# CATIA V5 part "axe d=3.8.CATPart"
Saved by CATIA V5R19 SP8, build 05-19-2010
Part number: axe d=3.8
Revision: ANY
Definition: UNKNOWN
Nomenclature: axe d=3.8
Source: Unknown
Bounding box of the stored display mesh (mm): x 0 to 16, y -3 to 3, z -3 to 3
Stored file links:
  D:\Documents\1_Travail\1 - ac-limoges.fr\ac-limoges.fr\Emmanuel Maynard - STI2D_Turgot\2 -2I2D\2_SEQUENCE_Serrure_Biométrique\5-Spé_ITEC\Serrure_Bio_Eleve\axe d=3.8.CATPart
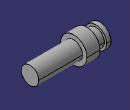
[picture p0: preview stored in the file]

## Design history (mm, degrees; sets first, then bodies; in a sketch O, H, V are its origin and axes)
Body1 "Révolution1" (main body)
  Solid1: solid without history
